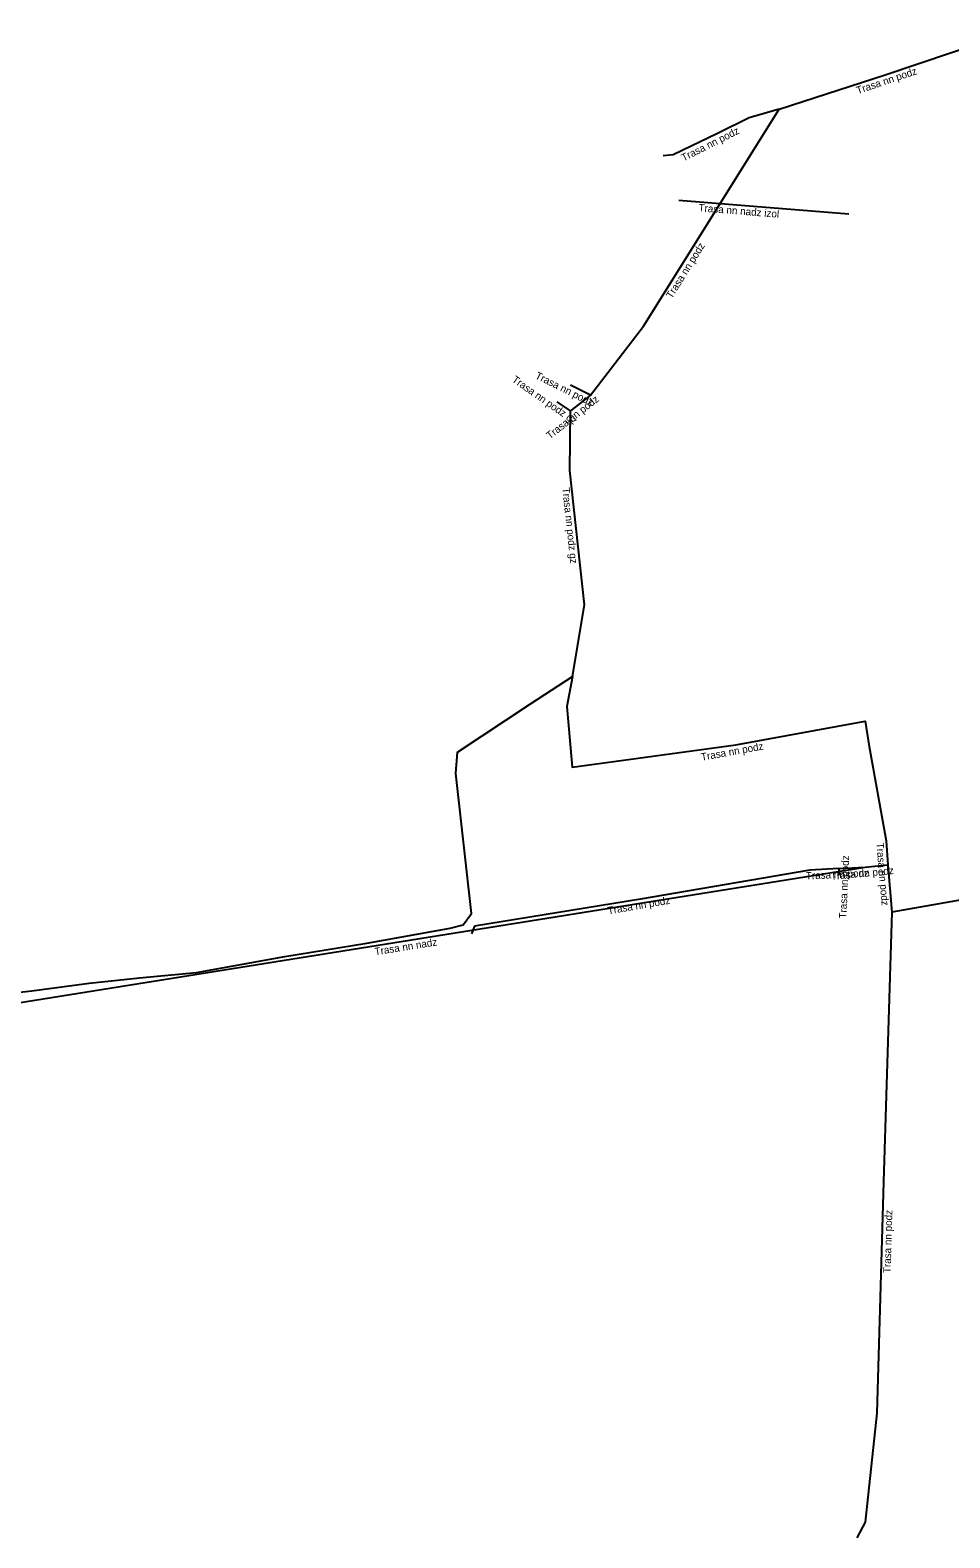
# Model space of a CAD drawing. Extents: x -682605 to -681948, y -1059884 to -1059661.
# Drawn here: x -682140.7 to -682078.5, y -1059823.8 to -1059721.8 of the extents above; entities that cross this region are included whole.
import ezdxf

# ---------------------------------------------------------------- set-up
doc = ezdxf.new("R2010")
doc.units = 0
doc.layers.add('Popiskový text - Ostatní atributy Trasy', color=7, linetype='Continuous')
doc.layers.add('Spojnice NN', color=7, linetype='Continuous')

msp = doc.modelspace()

# ---------------------------------------------------------------- linework, layer by layer
at = {"layer": 'Spojnice NN'}
for points in [[(-682090.02, -1059727.12), (-682082.85, -1059724.8), (-682073.88, -1059721.78)], [(-682102.77, -1059746.48), (-682099.19, -1059741.81), (-682090.02, -1059727.12)], [(-682090.02, -1059727.12), (-682092.06, -1059727.71), (-682094.18, -1059728.78), (-682097.18, -1059730.21), (-682097.86, -1059730.28)], [(-682096.81, -1059733.27), (-682085.31, -1059734.2)], [(-682102.77, -1059746.48), (-682104.13, -1059745.8)], [(-682102.77, -1059746.48), (-682104.12, -1059747.54)], [(-682104.12, -1059747.54), (-682105.02, -1059746.91)], [(-682104, -1059765.49), (-682103.18, -1059760.66), (-682104.17, -1059751.56), (-682104.12, -1059747.54)], [(-682144.97, -1059787.26), (-682140.54, -1059786.75), (-682136.66, -1059786.25), (-682133.27, -1059785.87), (-682129.42, -1059785.53), (-682123.44, -1059784.44), (-682117.89, -1059783.54), (-682112.27, -1059782.52), (-682111.38, -1059782.3), (-682110.81, -1059781.54), (-682111.88, -1059772.07), (-682111.76, -1059770.62), (-682106.83, -1059767.35), (-682104, -1059765.49)], [(-682104, -1059765.49), (-682104.38, -1059767.53), (-682104.01, -1059771.64), (-682092.96, -1059770.12), (-682084.2, -1059768.53), (-682083.93, -1059770.24), (-682082.78, -1059776.61), (-682082.68, -1059778.24)], [(-682045.14, -1059774.29), (-682048.09, -1059775.45), (-682055.93, -1059777.51), (-682063.42, -1059778.26), (-682064.54, -1059778.39), (-682065.53, -1059778.47), (-682082.4, -1059781.44)], [(-682144.43, -1059788.05), (-682084.21, -1059778.39)], [(-682085.98, -1059778.48), (-682087.94, -1059778.6), (-682099.39, -1059780.56), (-682110.62, -1059782.39), (-682110.81, -1059782.91)], [(-682085.98, -1059778.48), (-682086, -1059778.93)], [(-682085.98, -1059778.48), (-682084.21, -1059778.39)], [(-682084.21, -1059778.39), (-682082.68, -1059778.24)], [(-682082.68, -1059778.24), (-682082.4, -1059781.44)], [(-682082.4, -1059781.44), (-682082.96, -1059799.69), (-682083.41, -1059815.33), (-682084.2, -1059822.7), (-682084.78, -1059823.76)]]:
    msp.add_lwpolyline(points, dxfattribs=at)

# ---------------------------------------------------------------- texts
at = {"layer": 'Popiskový text - Ostatní atributy Trasy'}
for s, rotation, p in [('Trasa nn podz', 18.6072, (-682084.71, -1059726.11)), ('Trasa nn podz', 26.8163, (-682096.48, -1059730.67)), ('Trasa nn nadz izol', 355.3642, (-682095.49, -1059734.03)), ('Trasa nn podz', 58.0262, (-682097.28, -1059739.98)), ('Trasa nn podz gz', 325.008, (-682108.13, -1059745.52)), ('Trasa nn podz', 333.4349, (-682106.56, -1059745.31)), ('Trasa nn podz', 38.1385, (-682105.52, -1059749.47)), ('Trasa nn podz gz', 276.2089, (-682104.69, -1059752.75)), ('Trasa nn podz', 10.2876, (-682095.26, -1059771.2)), ('Trasa nn podz', 275.0006, (-682083.46, -1059776.76)), ('Trasa nn podz', 87.4552, (-682085.48, -1059781.88)), ('Trasa nn podz', 2.9108, (-682088.21, -1059779.24)), ('Trasa nn podz', 5.5993, (-682086.51, -1059779.27)), ('Trasa nn podz', 9.7137, (-682101.57, -1059781.59)), ('Trasa nn nadz', 9.1133, (-682117.33, -1059784.36)), ('Trasa nn podz', 88.3519, (-682082.49, -1059805.86))]:
    msp.add_text(s, height=0.5, rotation=rotation, dxfattribs=at).set_placement(p)

doc.saveas('drawing.dxf')
